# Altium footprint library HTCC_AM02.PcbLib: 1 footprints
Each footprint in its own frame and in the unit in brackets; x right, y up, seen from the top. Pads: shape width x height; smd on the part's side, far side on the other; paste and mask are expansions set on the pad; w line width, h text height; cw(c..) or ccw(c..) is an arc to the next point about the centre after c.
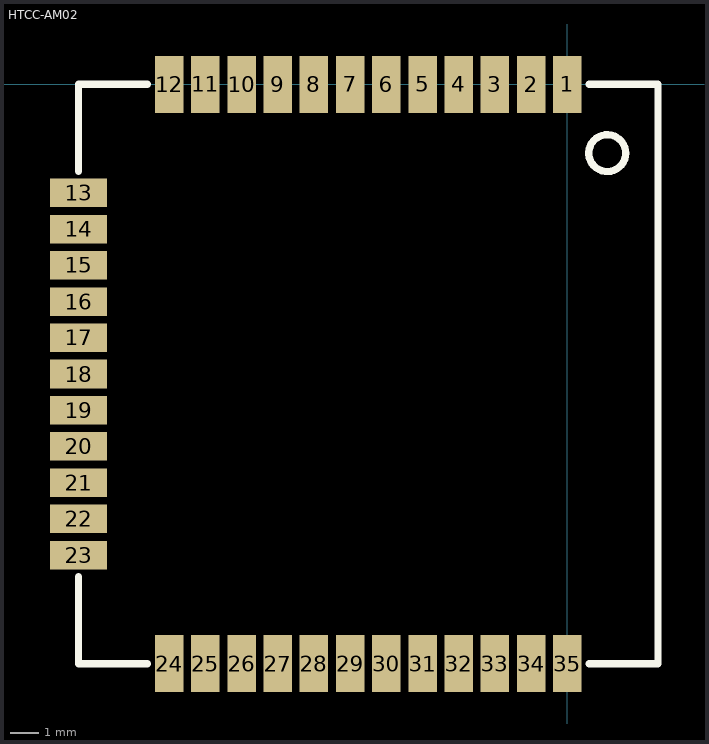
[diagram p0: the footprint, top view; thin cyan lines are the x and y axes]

## HTCC-AM02 [mm]
pads (35):
  rect 1x2 smd: 1(0,0) 2(-1.27,0) 3(-2.54,0) 4(-3.81,0) 5(-5.08,0) 6(-6.35,0) 7(-7.62,0) 8(-8.89,0) 9(-10.16,0) 10(-11.43,0) 11(-12.7,0) 12(-13.97,0) 24(-13.97,-20.32) 25(-12.7,-20.32) 26(-11.43,-20.32) 27(-10.16,-20.32) 28(-8.89,-20.32) 29(-7.62,-20.32) 30(-6.35,-20.32) 31(-5.08,-20.32) 32(-3.81,-20.32) 33(-2.54,-20.32) 34(-1.27,-20.32) 35(0,-20.32)
  rect 2x1 smd: 13(-17.145,-3.81) 14(-17.145,-5.08) 15(-17.145,-6.35) 16(-17.145,-7.62) 17(-17.145,-8.89) 18(-17.145,-10.16) 19(-17.145,-11.43) 20(-17.145,-12.7) 21(-17.145,-13.97) 22(-17.145,-15.24) 23(-17.145,-16.51)
Top Overlay:
  circle w0.254: c1.397,-2.413 r0.648
  lines w0.254: -17.145,-17.272 -17.145,-20.32 -14.732,-20.32 ; -17.145,-3.048 -17.145,0 -14.732,0 ; 0.762,-20.32 3.175,-20.32 3.175,0 0.762,0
